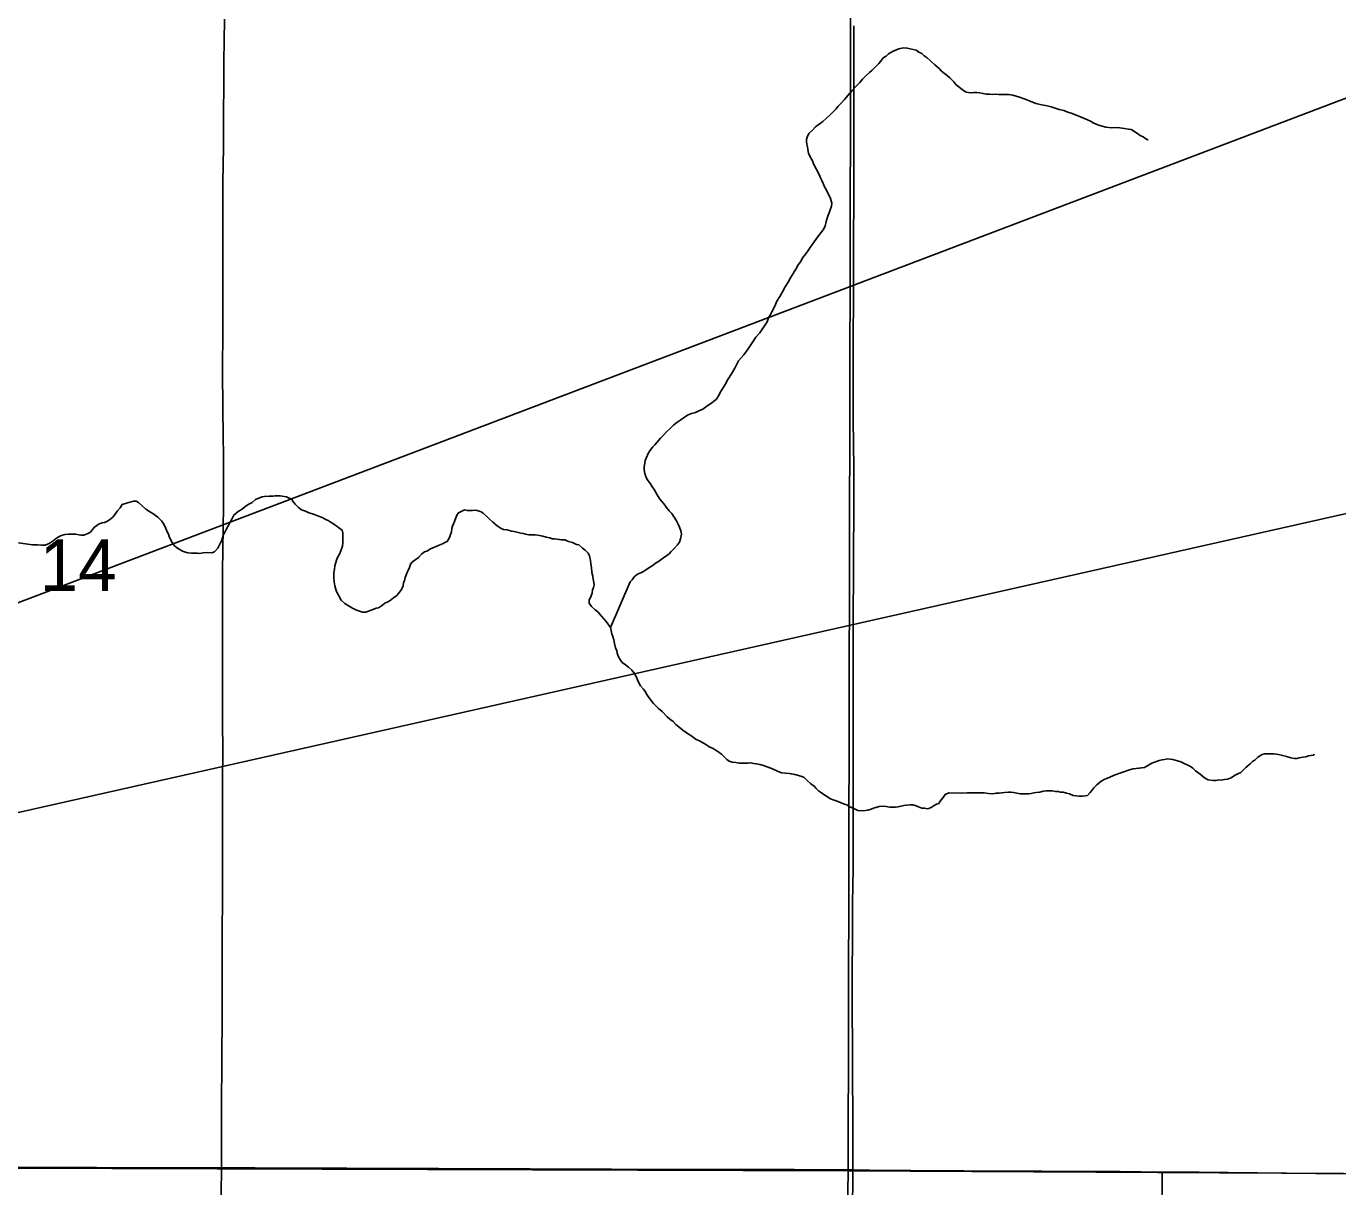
# Model space of a CAD drawing. Extents: x -17 to 88, y -5 to 22.
# Drawn here: x 7.061 to 8.123, y 17.134 to 18.074 of the extents above; entities that cross this region are included whole.
import ezdxf

# ---------------------------------------------------------------- set-up
doc = ezdxf.new("R2010")
doc.units = 0
for name, color, linetype in [('GM_X_County_Road', 7, 'Continuous'), ('GM_X_Minor_River', 7, 'Continuous'), ('GM_X_Section', 7, 'Continuous'), ('GM_X_Section_Text', 7, 'Continuous'), ('GM_X_Township_Road', 7, 'Continuous'), ('TX_P_10', 7, 'Continuous')]:
    doc.layers.add(name, color=color, linetype=linetype)

msp = doc.modelspace()

# ---------------------------------------------------------------- linework, layer by layer
at = {"layer": 'GM_X_County_Road'}
for points in [[(6.7102, 17.1496), (6.7699, 17.1496), (6.8177, 17.1495), (6.8568, 17.1497), (6.8972, 17.1496), (6.9202, 17.1497), (6.9748, 17.1495), (7.0177, 17.1492), (7.0494, 17.1494), (7.1177, 17.1493), (7.1376, 17.1491), (7.219, 17.1491)], [(7.219, 17.1491), (7.2463, 17.1489), (7.4692, 17.1481), (7.5351, 17.1478), (7.6258, 17.1476), (7.683, 17.1476), (7.7306, 17.1473)], [(7.7306, 17.1473), (7.7439, 17.1471), (7.811, 17.1466), (7.8203, 17.1466), (7.9471, 17.1459), (7.9812, 17.1456)], [(7.9812, 17.1456), (7.9937, 17.1455), (8.0111, 17.1454), (8.1055, 17.1445), (8.2118, 17.1439), (8.2373, 17.1436), (8.3031, 17.1432), (8.3224, 17.1432), (8.3802, 17.1427), (8.4088, 17.1424), (8.4516, 17.142), (8.5181, 17.1416), (8.548, 17.1416), (8.6145, 17.1414), (8.6456, 17.1411), (8.7133, 17.1409), (8.7317, 17.1409)]]:
    msp.add_lwpolyline(points, dxfattribs=at)
at = {"layer": 'GM_X_Minor_River'}
for points in [[(7.6924, 17.8894), (7.6944, 17.892), (7.696, 17.8946), (7.6979, 17.8973), (7.6991, 17.8991), (7.7006, 17.901), (7.7018, 17.9029), (7.7045, 17.9063), (7.7065, 17.9089), (7.7081, 17.9119), (7.7089, 17.9157), (7.7097, 17.9183), (7.7105, 17.9206), (7.7113, 17.9225), (7.7121, 17.9251), (7.7133, 17.9281), (7.7134, 17.9304), (7.713, 17.9323), (7.7123, 17.9342), (7.7116, 17.9361), (7.7097, 17.9396), (7.709, 17.9415), (7.7075, 17.9438), (7.7064, 17.9465), (7.7053, 17.9488), (7.7042, 17.9511), (7.7032, 17.9538), (7.6987, 17.9622), (7.698, 17.9641), (7.6969, 17.966), (7.6955, 17.9691), (7.6947, 17.971), (7.694, 17.974), (7.6937, 17.976), (7.6933, 17.9782), (7.693, 17.9801), (7.693, 17.982), (7.6935, 17.9839), (7.695, 17.9869), (7.6981, 17.9899), (7.7004, 17.9922), (7.7032, 17.9944), (7.7062, 17.9966), (7.7093, 17.9992), (7.7124, 18.0022), (7.7147, 18.0044), (7.7167, 18.0067), (7.7186, 18.0089), (7.721, 18.0115), (7.7237, 18.0145), (7.7268, 18.0179), (7.7299, 18.0216), (7.733, 18.025), (7.7361, 18.0283), (7.7384, 18.0309), (7.7412, 18.0339), (7.7439, 18.0362), (7.7458, 18.038), (7.7485, 18.0406), (7.7516, 18.0436), (7.7532, 18.0455), (7.7551, 18.0481), (7.7574, 18.0496), (7.7593, 18.0514), (7.7613, 18.0525), (7.7632, 18.0536), (7.7678, 18.0555), (7.7712, 18.0562), (7.7746, 18.0561), (7.7818, 18.0544), (7.7841, 18.0529), (7.7863, 18.0517), (7.7882, 18.0498), (7.7908, 18.0482), (7.7938, 18.0455), (7.7968, 18.0424), (7.7987, 18.0408), (7.8006, 18.0393), (7.8024, 18.0373), (7.8047, 18.0354), (7.8069, 18.0338), (7.8092, 18.0319), (7.8122, 18.0288), (7.814, 18.0265), (7.8163, 18.0246), (7.8193, 18.0222), (7.8223, 18.0203), (7.8242, 18.0202), (7.8264, 18.0198), (7.8287, 18.0202), (7.831, 18.0201), (7.8333, 18.0197), (7.8359, 18.0193), (7.8386, 18.0188), (7.8412, 18.0188), (7.8439, 18.0184), (7.8462, 18.0187), (7.8485, 18.0186), (7.8511, 18.0186), (7.8538, 18.0185), (7.8568, 18.0185)], [(7.8568, 18.0185), (7.8602, 18.018), (7.8655, 18.0164), (7.8701, 18.0148), (7.8742, 18.0132), (7.8787, 18.0112), (7.8837, 18.01), (7.8878, 18.0092), (7.8912, 18.0084), (7.8943, 18.0075), (7.8977, 18.0063), (7.9014, 18.0055), (7.9048, 18.0043), (7.9082, 18.0031), (7.9169, 17.9995), (7.9207, 17.9979), (7.923, 17.9968), (7.9252, 17.9956), (7.9275, 17.9944), (7.9297, 17.9936), (7.9324, 17.9928), (7.9354, 17.992), (7.94, 17.9915), (7.9434, 17.9918), (7.9468, 17.9914), (7.9506, 17.9909), (7.9536, 17.9905), (7.9559, 17.9901), (7.9582, 17.9889), (7.9604, 17.9873), (7.9634, 17.9854), (7.9657, 17.9842), (7.9679, 17.9826), (7.9694, 17.9818), (7.9698, 17.9818)], [(7.5343, 17.5866), (7.5502, 17.6236), (7.5518, 17.6254), (7.5533, 17.6277), (7.5561, 17.6299), (7.5587, 17.631), (7.561, 17.6321), (7.5633, 17.6336), (7.5653, 17.6351), (7.5687, 17.6373), (7.5707, 17.6387), (7.573, 17.6402), (7.5753, 17.6417), (7.5772, 17.6432), (7.5799, 17.645), (7.5818, 17.6465), (7.5834, 17.6484), (7.5861, 17.651), (7.5884, 17.6536), (7.59, 17.6559), (7.5908, 17.6585), (7.5916, 17.6623), (7.5913, 17.6649), (7.5902, 17.668), (7.5891, 17.6703), (7.5877, 17.673), (7.5858, 17.6761), (7.584, 17.6791), (7.5817, 17.6811), (7.5795, 17.6838), (7.5776, 17.6865), (7.5758, 17.6888), (7.5743, 17.6907), (7.5721, 17.6942), (7.5706, 17.6965), (7.5695, 17.6984), (7.5676, 17.7011), (7.5665, 17.703), (7.5639, 17.7065), (7.5629, 17.7091), (7.5621, 17.7114), (7.5614, 17.7145), (7.5615, 17.7168), (7.5619, 17.7198), (7.5623, 17.7221), (7.5631, 17.7239), (7.5651, 17.7281), (7.5667, 17.7307), (7.5686, 17.733), (7.5702, 17.7348), (7.5717, 17.7367), (7.5748, 17.7401), (7.5768, 17.7423), (7.5795, 17.7453), (7.5826, 17.7479), (7.5853, 17.7505), (7.588, 17.7527), (7.5911, 17.7549), (7.5942, 17.7572), (7.5972, 17.759), (7.5999, 17.7601), (7.603, 17.7608), (7.6057, 17.7623), (7.6091, 17.7637), (7.6122, 17.7659), (7.616, 17.7685), (7.618, 17.77), (7.6199, 17.7715), (7.6223, 17.7753), (7.6234, 17.7775), (7.625, 17.7801), (7.627, 17.7835), (7.6293, 17.7877), (7.6321, 17.7922), (7.6348, 17.7967), (7.638, 17.8027), (7.6423, 17.8075), (7.6458, 17.8124), (7.6489, 17.8173), (7.652, 17.8218), (7.6551, 17.8255), (7.661, 17.8342), (7.6622, 17.8376), (7.6638, 17.8402), (7.665, 17.8424), (7.6673, 17.8469), (7.6689, 17.8511), (7.6713, 17.8549), (7.6736, 17.8586), (7.6756, 17.8627), (7.678, 17.8665), (7.6799, 17.8699), (7.6823, 17.8736), (7.6842, 17.877), (7.6862, 17.8804), (7.6881, 17.883), (7.6901, 17.8864), (7.6924, 17.8894)], [(7.2016, 17.6467), (7.2039, 17.6471), (7.2077, 17.6474), (7.2112, 17.6473), (7.2135, 17.648), (7.2162, 17.651), (7.2193, 17.6574), (7.2205, 17.6612), (7.2229, 17.6661), (7.2245, 17.6691), (7.2261, 17.6721), (7.2277, 17.6751), (7.2292, 17.6778), (7.2312, 17.6796), (7.2335, 17.6811), (7.2358, 17.6826), (7.2381, 17.6844), (7.2408, 17.6863), (7.2439, 17.6881), (7.2466, 17.6903), (7.25, 17.6918), (7.2519, 17.6925), (7.2538, 17.6929), (7.2576, 17.6932), (7.2607, 17.6931), (7.2626, 17.6935), (7.2645, 17.6934), (7.2664, 17.6934), (7.2683, 17.693), (7.2717, 17.6925), (7.274, 17.6914), (7.2758, 17.6909), (7.277, 17.689), (7.2788, 17.6867), (7.2814, 17.684), (7.284, 17.6821), (7.2871, 17.6809), (7.2897, 17.6797), (7.2927, 17.6789), (7.295, 17.678), (7.2976, 17.6769), (7.3007, 17.6757), (7.3037, 17.6741), (7.3056, 17.6733), (7.3078, 17.6717), (7.3097, 17.6706), (7.3149, 17.667), (7.3168, 17.6655), (7.3175, 17.6632), (7.3174, 17.6579), (7.3174, 17.6552), (7.317, 17.6526), (7.3157, 17.6488), (7.3146, 17.6462), (7.3134, 17.6439), (7.3126, 17.642), (7.3114, 17.6386), (7.311, 17.6367), (7.3105, 17.6341), (7.3101, 17.6311), (7.31, 17.6288), (7.31, 17.6269), (7.3103, 17.6238), (7.311, 17.6204), (7.3121, 17.6166), (7.3128, 17.6147), (7.3139, 17.6128), (7.3161, 17.6089), (7.3191, 17.6062), (7.3225, 17.6039), (7.3251, 17.6023), (7.3278, 17.6011), (7.3308, 17.5999), (7.3334, 17.5991), (7.3361, 17.5991), (7.3426, 17.6016), (7.3445, 17.6023), (7.3464, 17.6027), (7.3495, 17.6049), (7.3514, 17.6064), (7.3538, 17.6075), (7.3557, 17.6086), (7.3584, 17.6108), (7.3611, 17.6126), (7.3634, 17.6153), (7.365, 17.6175), (7.3662, 17.6205), (7.3666, 17.6228), (7.3674, 17.6247), (7.3678, 17.6273), (7.369, 17.63), (7.3698, 17.6322), (7.371, 17.6345), (7.3722, 17.6379), (7.3737, 17.6398), (7.3757, 17.6412), (7.3788, 17.6435), (7.3815, 17.6464), (7.3834, 17.6479), (7.3853, 17.6486), (7.3884, 17.6505)], [(7.0547, 17.6552), (7.0661, 17.6538), (7.0699, 17.6538), (7.0733, 17.6533), (7.0763, 17.6533), (7.0794, 17.6547), (7.0828, 17.6569), (7.0855, 17.6592), (7.0886, 17.661), (7.0921, 17.6621), (7.0951, 17.6624), (7.0985, 17.6623), (7.1012, 17.6623), (7.1035, 17.6619), (7.1054, 17.6615), (7.1076, 17.6614), (7.1103, 17.6625), (7.113, 17.664), (7.1146, 17.6662), (7.1161, 17.6681), (7.12, 17.6707), (7.1223, 17.6714), (7.1242, 17.6717), (7.1261, 17.6725), (7.1284, 17.6739), (7.1311, 17.6762), (7.133, 17.6784), (7.1346, 17.681), (7.1369, 17.6836), (7.1385, 17.6863), (7.142, 17.6874), (7.1477, 17.6891), (7.15, 17.6891), (7.1519, 17.6879), (7.1545, 17.6856), (7.1578, 17.6825), (7.1616, 17.6802), (7.1635, 17.679), (7.1657, 17.6774), (7.1676, 17.6762), (7.1706, 17.6731), (7.1717, 17.6712), (7.1728, 17.6693), (7.1739, 17.667), (7.175, 17.6643), (7.1761, 17.6624), (7.1768, 17.6605), (7.1775, 17.6586), (7.179, 17.6555), (7.1809, 17.6528), (7.1835, 17.6509), (7.1876, 17.6485), (7.1899, 17.6477), (7.1918, 17.6473), (7.1948, 17.6469), (7.1975, 17.6468), (7.1997, 17.6468), (7.2016, 17.6467)], [(7.3884, 17.6505), (7.3903, 17.6512), (7.393, 17.6523), (7.3953, 17.6534), (7.398, 17.6545), (7.3999, 17.6556), (7.4018, 17.6563), (7.4038, 17.6597), (7.4046, 17.662), (7.4054, 17.6642), (7.4058, 17.6669), (7.4062, 17.6688), (7.407, 17.6706), (7.4078, 17.6725), (7.4098, 17.6778), (7.411, 17.6797), (7.416, 17.6819), (7.4182, 17.6815), (7.4205, 17.6814), (7.4224, 17.6814), (7.4251, 17.6817), (7.427, 17.6813), (7.4293, 17.6805), (7.4311, 17.6793), (7.4341, 17.6766), (7.436, 17.6747), (7.439, 17.672), (7.4423, 17.6692), (7.4457, 17.6669), (7.4476, 17.6661), (7.4506, 17.6657), (7.4541, 17.6648), (7.4563, 17.6644), (7.4582, 17.664), (7.4616, 17.6632), (7.4635, 17.6628), (7.4654, 17.6623), (7.4681, 17.6619), (7.4707, 17.6619), (7.473, 17.6618), (7.4753, 17.6614), (7.4794, 17.6606), (7.4821, 17.6598), (7.4851, 17.6593), (7.487, 17.6585), (7.4889, 17.6585), (7.4927, 17.658), (7.4946, 17.6576), (7.4973, 17.6576), (7.5003, 17.6564), (7.5033, 17.6556), (7.5067, 17.654), (7.5086, 17.6536), (7.5116, 17.6509), (7.5138, 17.6493), (7.5161, 17.647), (7.5172, 17.6447), (7.5179, 17.6409), (7.5182, 17.6382), (7.5189, 17.6352), (7.5192, 17.6313), (7.5199, 17.6283), (7.5202, 17.626), (7.5206, 17.6233), (7.5209, 17.6214), (7.5205, 17.6192), (7.5197, 17.6173), (7.5193, 17.6146), (7.5181, 17.6109), (7.5169, 17.609), (7.5168, 17.6063), (7.5187, 17.6036), (7.5217, 17.6009), (7.5239, 17.5994), (7.5269, 17.5959), (7.5288, 17.5936), (7.5306, 17.5916), (7.5343, 17.5866), (7.5347, 17.5844), (7.5354, 17.5817), (7.5361, 17.5794), (7.5368, 17.5767), (7.5375, 17.5737), (7.5382, 17.5702), (7.5393, 17.5679), (7.5397, 17.566), (7.5404, 17.5634), (7.5422, 17.5603), (7.5437, 17.5584), (7.5463, 17.5564), (7.5489, 17.5545), (7.5516, 17.5521), (7.5538, 17.5491), (7.5556, 17.5456), (7.5567, 17.5429), (7.5585, 17.5395), (7.5608, 17.5368), (7.5623, 17.5349), (7.5637, 17.5325), (7.5652, 17.5299), (7.5671, 17.5275)], [(7.5671, 17.5275), (7.5689, 17.5252), (7.5712, 17.5229), (7.573, 17.521), (7.576, 17.5186), (7.5801, 17.5144), (7.5824, 17.5125), (7.585, 17.5105), (7.5872, 17.5082), (7.5899, 17.5059), (7.5929, 17.5035), (7.5955, 17.5016), (7.5974, 17.5004), (7.5992, 17.4992), (7.6037, 17.4961), (7.6064, 17.4949), (7.6083, 17.4937), (7.6113, 17.4918), (7.6146, 17.4898), (7.6169, 17.489), (7.6203, 17.4867), (7.624, 17.484), (7.6267, 17.4813), (7.6285, 17.4797), (7.6304, 17.4785), (7.6327, 17.4777), (7.6357, 17.4773), (7.6384, 17.4769), (7.6414, 17.4768), (7.6456, 17.4767), (7.6479, 17.4771), (7.6501, 17.4766), (7.6524, 17.4762), (7.6551, 17.4758), (7.6581, 17.475), (7.6611, 17.4738), (7.6653, 17.4722), (7.6694, 17.4702), (7.6728, 17.469), (7.6758, 17.4686), (7.6789, 17.4685), (7.6808, 17.4681), (7.6834, 17.4677), (7.6865, 17.4668), (7.6891, 17.466), (7.691, 17.4652), (7.6936, 17.4629), (7.6966, 17.4602), (7.6992, 17.4583), (7.7007, 17.4563), (7.7026, 17.4544), (7.7052, 17.4528), (7.712, 17.4481), (7.7146, 17.447), (7.7169, 17.4462), (7.7191, 17.4454), (7.721, 17.4446), (7.7229, 17.4438), (7.7256, 17.443), (7.7282, 17.4414), (7.7312, 17.4402), (7.7346, 17.4386), (7.738, 17.4382), (7.7407, 17.4385), (7.7426, 17.4388), (7.7453, 17.4396), (7.7472, 17.4403), (7.7491, 17.441), (7.7518, 17.4417), (7.7548, 17.442), (7.7575, 17.4416), (7.7605, 17.4412), (7.7632, 17.4411), (7.7651, 17.4411), (7.767, 17.4414), (7.7696, 17.4421), (7.7719, 17.4425), (7.7742, 17.4428), (7.7769, 17.4431), (7.7792, 17.4431), (7.7818, 17.4423), (7.7837, 17.4415), (7.7863, 17.4403), (7.7886, 17.4403), (7.7913, 17.4398), (7.7939, 17.4409), (7.7963, 17.4424), (7.7982, 17.4435), (7.8001, 17.4442), (7.8013, 17.4461), (7.8036, 17.4491), (7.8052, 17.4513), (7.8082, 17.4528), (7.8185, 17.4526), (7.8231, 17.4529), (7.828, 17.4528), (7.8326, 17.4527), (7.8368, 17.4527), (7.8405, 17.4522), (7.844, 17.4521), (7.8466, 17.4525)], [(7.8466, 17.4525), (7.8489, 17.4524), (7.8512, 17.4528), (7.8535, 17.4531), (7.8565, 17.4534), (7.8584, 17.4534), (7.8607, 17.453), (7.8634, 17.4525), (7.866, 17.4521), (7.8679, 17.4521), (7.8702, 17.452), (7.8729, 17.452), (7.8751, 17.4523), (7.8771, 17.4527), (7.879, 17.453), (7.882, 17.4533), (7.8847, 17.454), (7.887, 17.4544), (7.8896, 17.4543), (7.8923, 17.4543), (7.8946, 17.4539), (7.8968, 17.4538), (7.8987, 17.4534), (7.901, 17.4534), (7.9037, 17.4526), (7.9059, 17.4521), (7.9089, 17.4506), (7.9139, 17.4501), (7.9165, 17.45), (7.9188, 17.4504), (7.9207, 17.4507), (7.9227, 17.453), (7.9242, 17.4548), (7.9258, 17.4567), (7.9281, 17.4593), (7.9316, 17.4623), (7.9347, 17.4638), (7.9381, 17.4652), (7.9423, 17.467), (7.9546, 17.4714), (7.9576, 17.4721), (7.9599, 17.4724), (7.9622, 17.4727), (7.9645, 17.4731), (7.9668, 17.4734), (7.9687, 17.4745), (7.9726, 17.4767), (7.9756, 17.4778), (7.9787, 17.4789), (7.981, 17.4796), (7.9829, 17.4799), (7.9855, 17.4803), (7.9897, 17.4798), (7.9935, 17.4786), (7.9961, 17.4778), (7.9988, 17.4766), (8.0014, 17.4754), (8.0041, 17.4742), (8.0059, 17.4727), (8.0082, 17.4707), (8.01, 17.4692), (8.0119, 17.468), (8.0153, 17.4649), (8.0183, 17.4633), (8.0225, 17.4629), (8.0248, 17.4628), (8.027, 17.4632), (8.0289, 17.4631), (8.0316, 17.4635), (8.0339, 17.4638), (8.037, 17.4649), (8.0397, 17.4667), (8.0424, 17.4682), (8.0447, 17.4693), (8.0489, 17.4734), (8.0524, 17.4764), (8.0543, 17.4782), (8.0562, 17.4793), (8.0586, 17.4816), (8.062, 17.4838), (8.0639, 17.4845), (8.0666, 17.4845), (8.0715, 17.4844), (8.0753, 17.4839), (8.0787, 17.4831), (8.0818, 17.4823), (8.0852, 17.4811), (8.0882, 17.4806), (8.0901, 17.4806), (8.092, 17.481), (8.0951, 17.4817), (8.0974, 17.482), (8.0997, 17.4827), (8.1016, 17.4831), (8.1038, 17.4834), (8.1038, 17.4834), (8.1042, 17.4841)]]:
    msp.add_lwpolyline(points, dxfattribs=at)
at = {"layer": 'GM_X_Section'}
for points in [[(6.7087, 18.155), (7.729, 18.1476), (7.7267, 17.1466), (6.7038, 17.1499)], [(8.7311, 18.1404), (8.7296, 17.1413), (7.7267, 17.1466), (7.729, 18.1476)], [(6.7038, 17.1499), (7.7267, 17.1466), (7.7116, 16.1511), (6.7095, 16.1492)], [(7.7267, 17.1466), (8.7296, 17.1413), (8.7243, 16.1407), (7.7116, 16.1511)]]:
    msp.add_lwpolyline(points, close=True, dxfattribs=at)
at = {"layer": 'GM_X_Township_Road'}
for points in [[(7.219, 17.1491), (7.2191, 17.1988), (7.2196, 17.2734), (7.2196, 17.3131), (7.2197, 17.3374), (7.2199, 17.3697), (7.2199, 17.4225), (7.2199, 17.4536), (7.2201, 17.4964), (7.22, 17.5007), (7.22, 17.5076), (7.22, 17.52), (7.22, 17.5467), (7.2199, 17.5598), (7.2198, 17.571), (7.2199, 17.5859), (7.2199, 17.5939), (7.2199, 17.6132), (7.22, 17.628), (7.2203, 17.654), (7.2204, 17.6633), (7.2207, 17.6888), (7.2207, 17.7154), (7.2206, 17.7277), (7.2204, 17.7402), (7.22, 17.7924), (7.2201, 17.8297), (7.2201, 17.8458), (7.2201, 17.8738), (7.2202, 17.903), (7.2203, 17.9471), (7.2206, 17.9757), (7.2206, 17.9974), (7.2209, 18.0322), (7.2211, 18.0456), (7.2212, 18.0617), (7.2214, 18.0795)], [(7.7306, 17.1473), (7.7306, 17.1492), (7.7306, 17.1628), (7.7305, 17.1821), (7.7304, 17.1989), (7.7303, 17.2163), (7.7302, 17.2467), (7.73, 17.2778), (7.73, 17.3089), (7.7302, 17.3325), (7.7302, 17.3412), (7.7302, 17.3635), (7.7307, 17.3915), (7.7309, 17.4232), (7.7307, 17.4828), (7.7308, 17.5095), (7.7307, 17.5369), (7.7307, 17.5642), (7.7308, 17.5797), (7.7311, 17.6475), (7.7313, 17.6804), (7.7312, 17.7159), (7.7309, 17.755), (7.7309, 17.7681), (7.7307, 17.7861), (7.7307, 17.7985), (7.7309, 17.8246), (7.731, 17.85), (7.731, 17.8865), (7.731, 17.9008), (7.7311, 17.912), (7.7312, 17.9225), (7.7313, 17.9375), (7.7313, 17.9499), (7.7313, 17.9617), (7.7312, 17.971), (7.7312, 17.9859), (7.7312, 17.9983), (7.7312, 18.0139), (7.7313, 18.0412), (7.7313, 18.0742)], [(7.2163, 16.6488), (7.2167, 16.6719), (7.2166, 16.7091), (7.2169, 16.7731), (7.2171, 16.7992), (7.2176, 16.8551), (7.2176, 16.8756), (7.2177, 16.9166), (7.2178, 16.9324), (7.2178, 16.9857), (7.218, 17.0162), (7.2182, 17.0448), (7.2183, 17.0609), (7.2184, 17.0796), (7.2186, 17.1069), (7.219, 17.1491)], [(7.7234, 16.6475), (7.7238, 16.6803), (7.7239, 16.7008), (7.7244, 16.7325), (7.7248, 16.758), (7.7252, 16.7822), (7.7253, 16.789), (7.7258, 16.8089), (7.7263, 16.8275), (7.7267, 16.8548), (7.727, 16.8933), (7.7274, 16.9107), (7.7276, 16.925), (7.7285, 16.9585), (7.7287, 16.9715), (7.7292, 16.9958), (7.7296, 17.0274), (7.7298, 17.0541), (7.7298, 17.061), (7.7299, 17.0734), (7.7306, 17.1473)], [(7.9751, 16.6463), (7.9751, 16.6483), (7.9751, 16.6539), (7.9753, 16.6881), (7.9758, 16.7241), (7.9762, 16.7608), (7.9765, 16.7937), (7.9774, 16.8471), (7.9781, 16.8838), (7.9787, 16.9161), (7.9788, 16.9297), (7.9792, 16.9869), (7.9795, 17.0055), (7.98, 17.0397), (7.9802, 17.0571), (7.9803, 17.0813), (7.9808, 17.1092), (7.9812, 17.1456)]]:
    msp.add_lwpolyline(points, dxfattribs=at)
at = {"layer": 'TX_P_10'}
msp.add_lwpolyline([(5.9567, 17.1898), (9.6824, 18.6059), (9.6824, 18.0286)], close=True, dxfattribs=at)

# ---------------------------------------------------------------- texts
at = {"layer": 'GM_X_Section_Text'}
msp.add_text('14', height=0.04186, rotation=0, dxfattribs=at).set_placement((7.0718, 17.6163))

doc.saveas('drawing.dxf')
